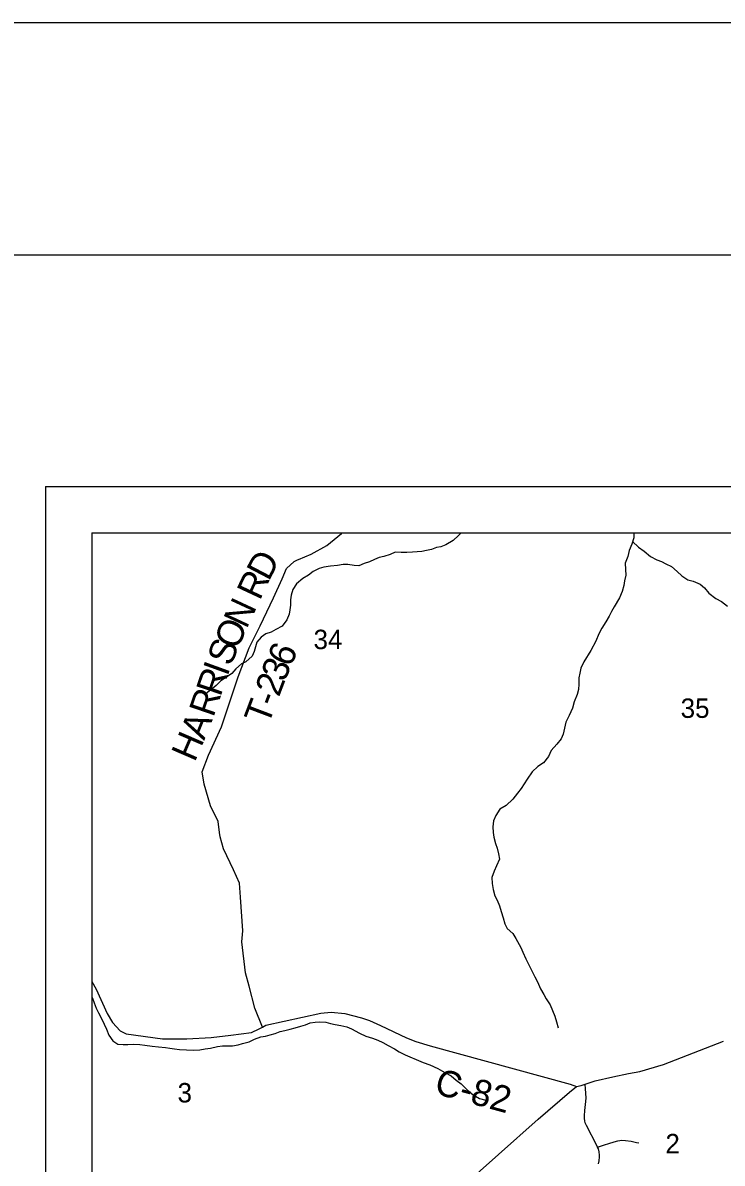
# Model space of a CAD drawing. Extents: x 0 to 34, y 0 to 22.
# Drawn here: x 1.951 to 3.459, y 19.541 to 22 of the extents above; entities that cross this region are included whole.
import ezdxf

# ---------------------------------------------------------------- set-up
doc = ezdxf.new("R2010")
doc.units = 0
for name, color, linetype in [('GM_X_County_Road', 7, 'Continuous'), ('GM_X_County_Road_Text', 7, 'Continuous'), ('GM_X_Minor_River', 7, 'Continuous'), ('GM_X_Section_Text', 7, 'Continuous'), ('GM_X_Township_Road', 7, 'Continuous'), ('GM_X_Township_Road_Text', 7, 'Continuous'), ('SH_Border', 7, 'Continuous'), ('SH_Cut_Line', 7, 'Continuous'), ('SH_Data', 7, 'Continuous')]:
    doc.layers.add(name, color=color, linetype=linetype)

msp = doc.modelspace()

# ---------------------------------------------------------------- linework, layer by layer
at = {"layer": 'GM_X_County_Road'}
for points in [[(2.1, 19.933), (2.1093, 19.9163), (2.1324, 19.8641), (2.144, 19.8443), (2.161, 19.8267), (2.1737, 19.8201), (2.2523, 19.8091), (2.3045, 19.8091), (2.3568, 19.8118), (2.3991, 19.8173), (2.4441, 19.8225), (2.4606, 19.8308), (2.4677, 19.8346), (2.4751, 19.8384), (2.5933, 19.8646), (2.6158, 19.8668), (2.645, 19.8635), (2.6812, 19.8542), (2.6988, 19.8487), (2.7219, 19.8382), (2.7785, 19.8111), (2.7982, 19.8034), (2.8293, 19.7941), (3.1312, 19.7117), (3.1446, 19.7065), (3.1546, 19.7085), (3.1639, 19.7116), (3.1851, 19.7186), (3.223, 19.7275), (3.2573, 19.7345), (3.2815, 19.7386), (3.3322, 19.7541), (3.4617, 19.8043)], [(3.192, 19.5394), (3.1935, 19.546), (3.1944, 19.5549), (3.1946, 19.5587), (3.1939, 19.5655), (3.192, 19.5719), (3.1904, 19.5755), (3.1812, 19.5933), (3.1737, 19.6079), (3.169, 19.6171), (3.1663, 19.6224), (3.1639, 19.628), (3.1628, 19.6325), (3.1621, 19.6375), (3.1622, 19.643), (3.1632, 19.6546), (3.1649, 19.6739), (3.1656, 19.6818), (3.1646, 19.7017), (3.1639, 19.7116)]]:
    msp.add_lwpolyline(points, dxfattribs=at)
at = {"layer": 'GM_X_Minor_River'}
for points in [[(2.8963, 20.9), (2.8906, 20.8947), (2.8788, 20.8834), (2.8628, 20.8744), (2.8526, 20.8703), (2.8427, 20.8688), (2.8321, 20.8643), (2.8211, 20.8621), (2.8112, 20.8603), (2.801, 20.8596), (2.7912, 20.8585), (2.7787, 20.8582), (2.7666, 20.8579), (2.7537, 20.8584), (2.7427, 20.8532), (2.7291, 20.8495), (2.7196, 20.8469), (2.709, 20.8428), (2.6983, 20.8379), (2.687, 20.8338), (2.6752, 20.8294), (2.6654, 20.8298), (2.6517, 20.8322), (2.6415, 20.8322), (2.6294, 20.83), (2.6143, 20.8282), (2.6002, 20.8261), (2.59, 20.8231), (2.5771, 20.8171), (2.5668, 20.8088), (2.5547, 20.8017), (2.541, 20.7901), (2.5329, 20.778), (2.5298, 20.7659), (2.5279, 20.7556), (2.5278, 20.7446), (2.527, 20.7344), (2.5254, 20.7249), (2.52, 20.7125), (2.5101, 20.6992), (2.4968, 20.6917), (2.4862, 20.6861), (2.4748, 20.6824), (2.4649, 20.6753), (2.4554, 20.6647), (2.4523, 20.6545), (2.4499, 20.6447), (2.4453, 20.6344), (2.4316, 20.622), (2.4221, 20.6179), (2.4103, 20.607), (2.4015, 20.5972), (2.3879, 20.5878), (2.378, 20.581), (2.3677, 20.5713), (2.3559, 20.5611), (2.343, 20.5517)], [(3.2682, 20.9), (3.2682, 20.8997), (3.2682, 20.8895), (3.2643, 20.8759), (3.2585, 20.8623), (3.2554, 20.849), (3.2496, 20.8346), (3.2507, 20.821), (3.251, 20.8088), (3.2486, 20.7971), (3.2467, 20.7869), (3.2435, 20.774), (3.2378, 20.7604), (3.2263, 20.7407), (3.2202, 20.7309), (3.2156, 20.7207), (3.2079, 20.7083), (3.1995, 20.695), (3.1933, 20.6822), (3.1864, 20.6667), (3.1761, 20.6463), (3.1608, 20.6221), (3.1542, 20.6085), (3.1523, 20.5975), (3.1496, 20.5873), (3.1502, 20.5736), (3.1494, 20.5623), (3.1463, 20.552), (3.1401, 20.5358), (3.1363, 20.5225), (3.129, 20.5063), (3.1217, 20.4923), (3.1193, 20.4794), (3.1158, 20.4661), (3.112, 20.4563), (3.1024, 20.4446), (3.0902, 20.431), (3.0848, 20.4182), (3.0734, 20.4046), (3.0612, 20.3963), (3.049, 20.3851), (3.0383, 20.3692), (3.0253, 20.3488), (3.0173, 20.3386), (3.0074, 20.3258), (2.9933, 20.3122), (2.9796, 20.3047), (2.9708, 20.2904), (2.9662, 20.279), (2.9646, 20.2661), (2.9653, 20.254), (2.9664, 20.2438), (2.97, 20.2301), (2.9738, 20.2202), (2.9767, 20.208), (2.9789, 20.1966), (2.9727, 20.1819), (2.9674, 20.1709), (2.9624, 20.1569), (2.963, 20.1444), (2.9648, 20.1311), (2.9689, 20.1178), (2.9738, 20.1079), (2.9786, 20.0961), (2.9823, 20.0836), (2.9867, 20.0699), (2.9904, 20.057), (2.9953, 20.0471), (3.0073, 20.0364), (3.0141, 20.0257), (3.0245, 20.006), (3.029, 19.9964), (3.0357, 19.982), (3.0432, 19.966), (3.0488, 19.9557), (3.0551, 19.9428), (3.0607, 19.9321), (3.067, 19.9169), (3.0745, 19.9047), (3.0798, 19.8952), (3.088, 19.8823), (3.0932, 19.8705), (3.0984, 19.8579), (3.1018, 19.8462), (3.1055, 19.8329)], [(3.2658, 20.8813), (3.2786, 20.8693), (3.2911, 20.8605), (3.3042, 20.8494), (3.3178, 20.8421), (3.328, 20.8387), (3.3378, 20.8333), (3.3499, 20.8275), (3.3619, 20.8168), (3.3717, 20.8073), (3.3852, 20.7992), (3.3962, 20.7957), (3.4113, 20.7896), (3.4211, 20.7815), (3.4304, 20.7701), (3.4455, 20.759), (3.4576, 20.7521), (3.4704, 20.7422)], [(2.1, 19.8995), (2.1009, 19.8972), (2.105, 19.8866), (2.109, 19.8755), (2.1139, 19.8656), (2.1217, 19.8504), (2.1262, 19.8405), (2.1314, 19.8303), (2.1366, 19.8169), (2.1449, 19.8048), (2.1554, 19.7975), (2.1672, 19.797), (2.1774, 19.7973), (2.1891, 19.798), (2.2031, 19.7972), (2.2137, 19.7952), (2.2296, 19.7932), (2.2432, 19.7916), (2.2583, 19.7907), (2.2681, 19.7888), (2.278, 19.7876), (2.2886, 19.7863), (2.3037, 19.7855), (2.3192, 19.7846), (2.3328, 19.7857), (2.3438, 19.7875), (2.3559, 19.7893), (2.3707, 19.7926), (2.3813, 19.7944), (2.3923, 19.794), (2.4029, 19.7939), (2.415, 19.7961), (2.4245, 19.7991), (2.4389, 19.8028), (2.4507, 19.8084), (2.4639, 19.8132), (2.4742, 19.8151), (2.484, 19.8177), (2.495, 19.821), (2.506, 19.8247), (2.5162, 19.8273), (2.5276, 19.8303), (2.5382, 19.8328), (2.5504, 19.8362), (2.5602, 19.8391), (2.5705, 19.844), (2.5815, 19.8454), (2.5913, 19.8461), (2.6042, 19.8449), (2.614, 19.8422), (2.6246, 19.8402), (2.637, 19.8382), (2.6495, 19.8351), (2.6593, 19.8305), (2.6767, 19.8217), (2.6902, 19.8151), (2.7046, 19.8105), (2.7167, 19.8062), (2.7272, 19.8016), (2.7385, 19.7947), (2.7521, 19.7874), (2.7623, 19.7813), (2.7751, 19.7748), (2.7853, 19.7701), (2.7989, 19.7647), (2.814, 19.7582), (2.8283, 19.7532), (2.8457, 19.7455), (2.8611, 19.7363), (2.8747, 19.7293), (2.8852, 19.7202), (2.8958, 19.7121), (2.9093, 19.6991), (2.9221, 19.6888), (2.936, 19.6804), (2.9492, 19.6769)]]:
    msp.add_lwpolyline(points, dxfattribs=at)
at = {"layer": 'GM_X_Township_Road'}
for points in [[(2.5435, 20.8419), (2.5454, 20.8426), (2.5727, 20.8542), (2.6061, 20.8726), (2.6384, 20.8986), (2.6387, 20.9)], [(2.3749, 20.254), (2.3719, 20.2777), (2.3556, 20.3113), (2.3422, 20.3584), (2.3378, 20.385), (2.3516, 20.4206), (2.3796, 20.4819), (2.4153, 20.5898), (2.4391, 20.6523), (2.4625, 20.6996), (2.4916, 20.7601), (2.5103, 20.8014), (2.5195, 20.823), (2.5363, 20.8388), (2.5435, 20.8419)], [(2.4677, 19.8346), (2.4514, 19.8756), (2.4393, 19.9229), (2.431, 19.9515), (2.4233, 20.0187), (2.425, 20.0423), (2.4204, 20.1146), (2.4184, 20.1451), (2.4052, 20.1736), (2.3837, 20.2187), (2.3761, 20.2451), (2.3749, 20.254)], [(2.7795, 19.1559), (2.788, 19.1708), (2.7923, 19.1841), (2.7944, 19.2276), (2.7931, 19.2721), (2.7952, 19.2996), (2.8028, 19.3363), (2.818, 19.3819), (2.8361, 19.4259), (2.8657, 19.4571), (2.891, 19.4833), (3.062, 19.6357), (3.1299, 19.694), (3.1446, 19.7065)], [(3.1904, 19.5755), (3.2056, 19.5804), (3.2149, 19.5833), (3.226, 19.5869), (3.2342, 19.5893), (3.2425, 19.5904), (3.2503, 19.5903), (3.2626, 19.5883), (3.2745, 19.586), (3.2793, 19.585)]]:
    msp.add_lwpolyline(points, dxfattribs=at)
at = {"layer": 'SH_Border'}
msp.add_lwpolyline([(1.5, 21.5), (33.5, 21.5), (33.5, 0.5), (1.5, 0.5)], close=True, dxfattribs=at)
at = {"layer": 'SH_Cut_Line'}
msp.add_lwpolyline([(0, 0), (34, 0), (34, 22), (0, 22)], close=True, dxfattribs=at)
at = {"layer": 'SH_Data'}
for p, q in [((2, 21), (9, 21)), ((2, 21), (2, 14)), ((2.1, 20.9), (2.1, 14.1)), ((2.1, 20.9), (8.9, 20.9))]:
    msp.add_line(p, q, dxfattribs=at)

# ---------------------------------------------------------------- texts
at = {"layer": 'GM_X_County_Road_Text'}
msp.add_text('C-82', height=0.05682, rotation=344.7151, dxfattribs=at).set_placement((2.8359, 19.6917))
at = {"layer": 'GM_X_Section_Text'}
for s, height, p in [('34', 0.04186, (2.5778, 20.6495)), ('35', 0.04186, (3.3695, 20.5012)), ('3', 0.0419, (2.2845, 19.672)), ('2', 0.0419, (3.3366, 19.5623))]:
    msp.add_text(s, height=height, rotation=0, dxfattribs=at).set_placement(p)
at = {"layer": 'GM_X_Township_Road_Text'}
for s, rotation, p in [('D', 62.4199, (2.4812, 20.7943)), ('R', 64.9536, (2.4618, 20.7526)), ('N', 65.03, (2.4333, 20.6914)), ('O', 66.269, (2.4133, 20.6459)), ('S', 68.8039, (2.3997, 20.6108)), ('6', 66.3765, (2.5282, 20.6087)), ('R', 71.3254, (2.377, 20.5453)), ('I', 70.1456, (2.3919, 20.5892)), ('3', 67.9912, (2.5153, 20.5769)), ('2', 69.1931, (2.5031, 20.5447)), ('R', 71.0045, (2.3617, 20.5008)), ('T', 69.2646, (2.4799, 20.4834)), ('-', 69.2468, (2.4949, 20.5231)), ('A', 68.0024, (2.3418, 20.4514)), ('H', 66.6426, (2.3215, 20.4042))]:
    msp.add_text(s, height=0.0568, rotation=rotation, dxfattribs=at).set_placement(p)

doc.saveas('drawing.dxf')
